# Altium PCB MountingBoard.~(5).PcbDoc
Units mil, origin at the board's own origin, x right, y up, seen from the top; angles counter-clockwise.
Board outline 3780 x 10000 mil, 4 copper layers (Top Layer, Internal Plane 1, Internal Plane 2, Bottom Layer); 23 components, 8 nets, 78 pads, 8 vias.
Unrouted connection lines stored in the file: 72.
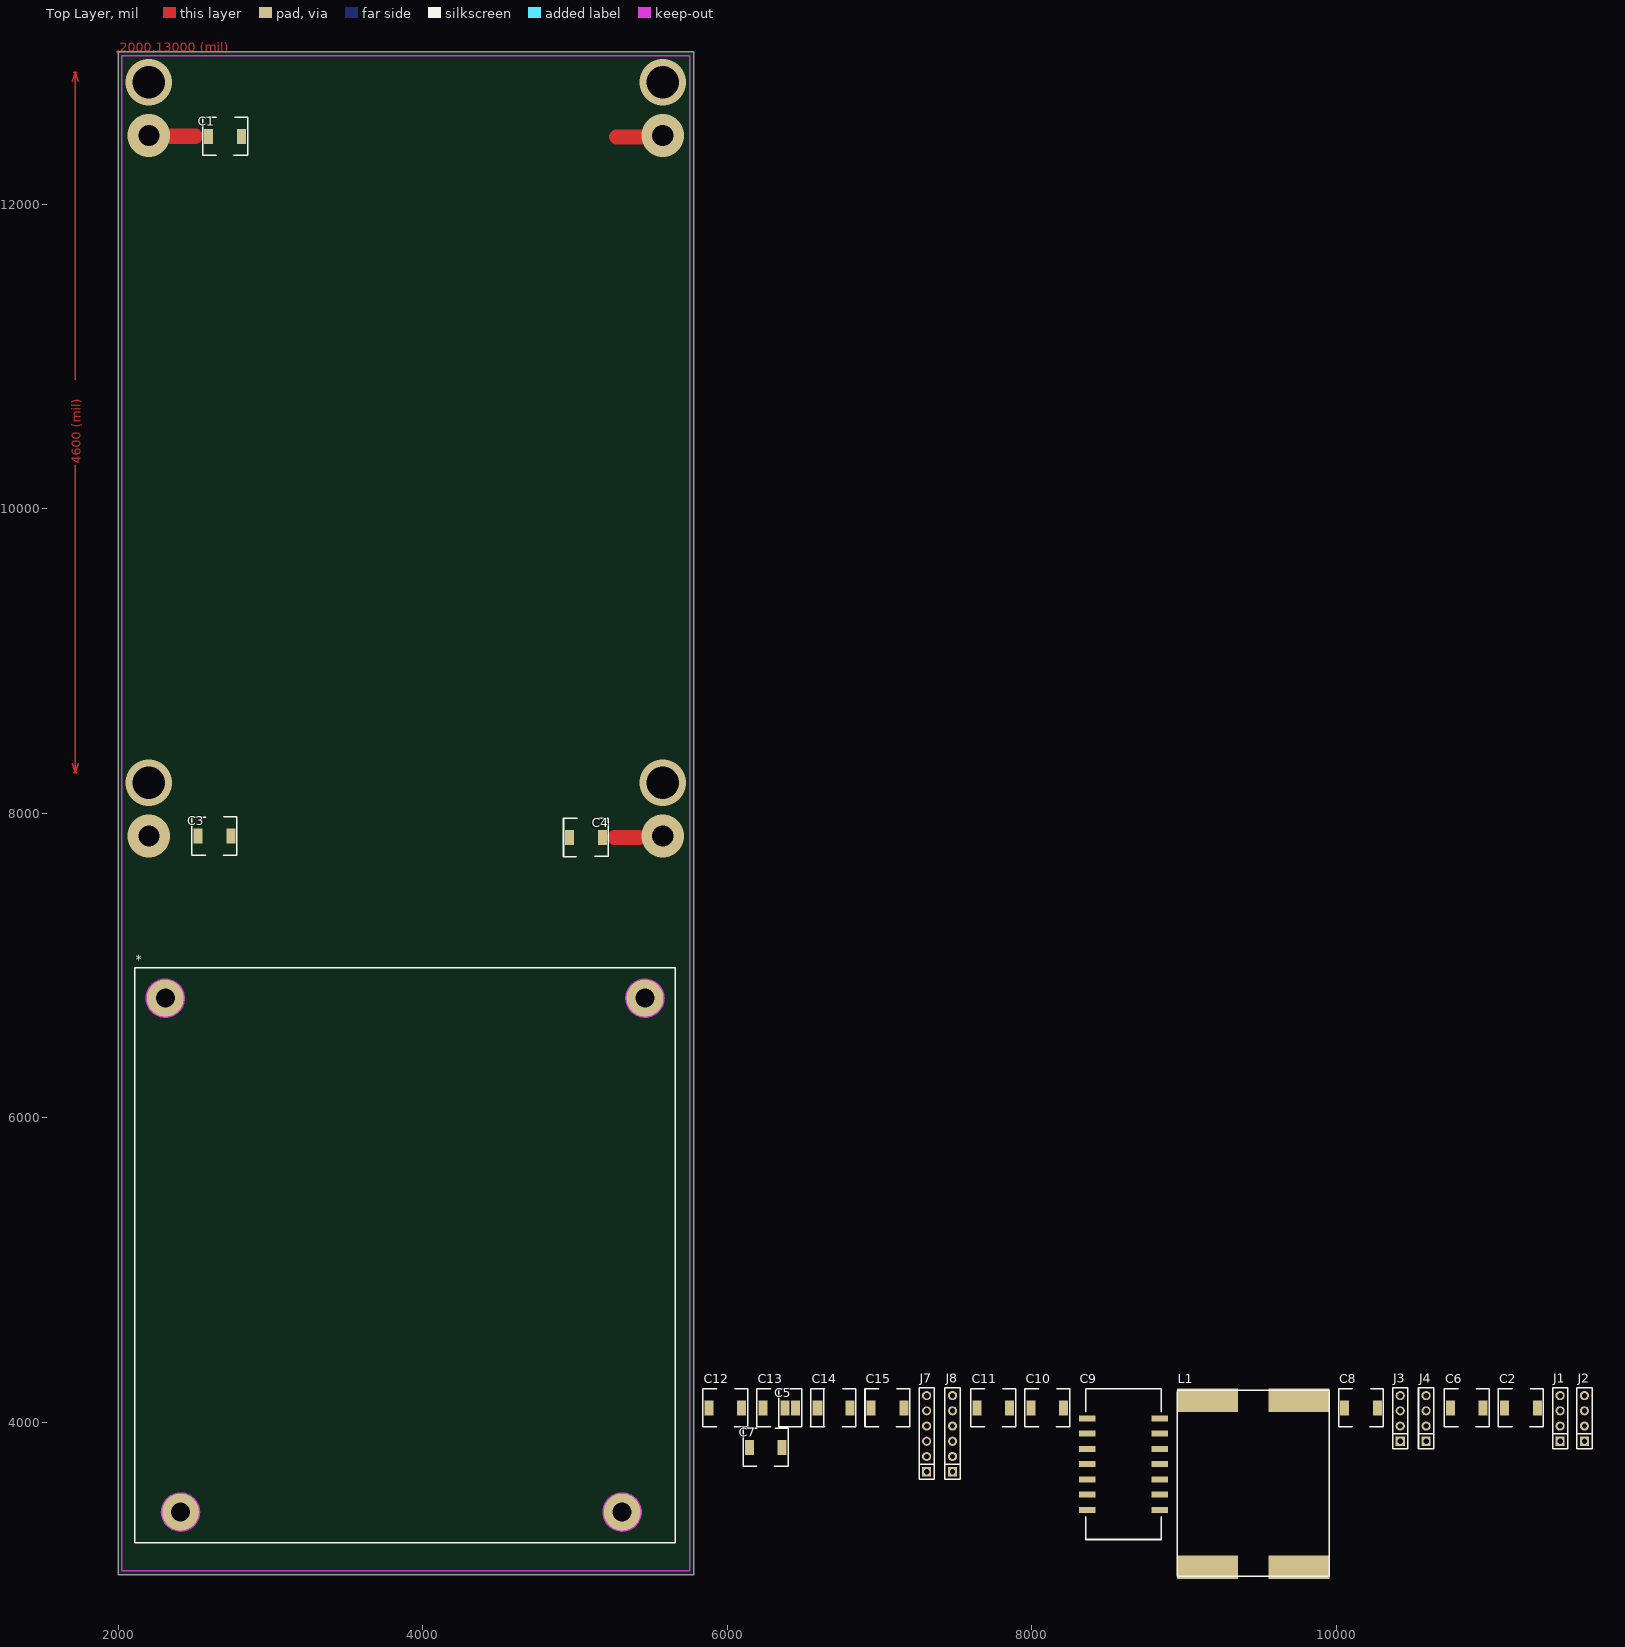
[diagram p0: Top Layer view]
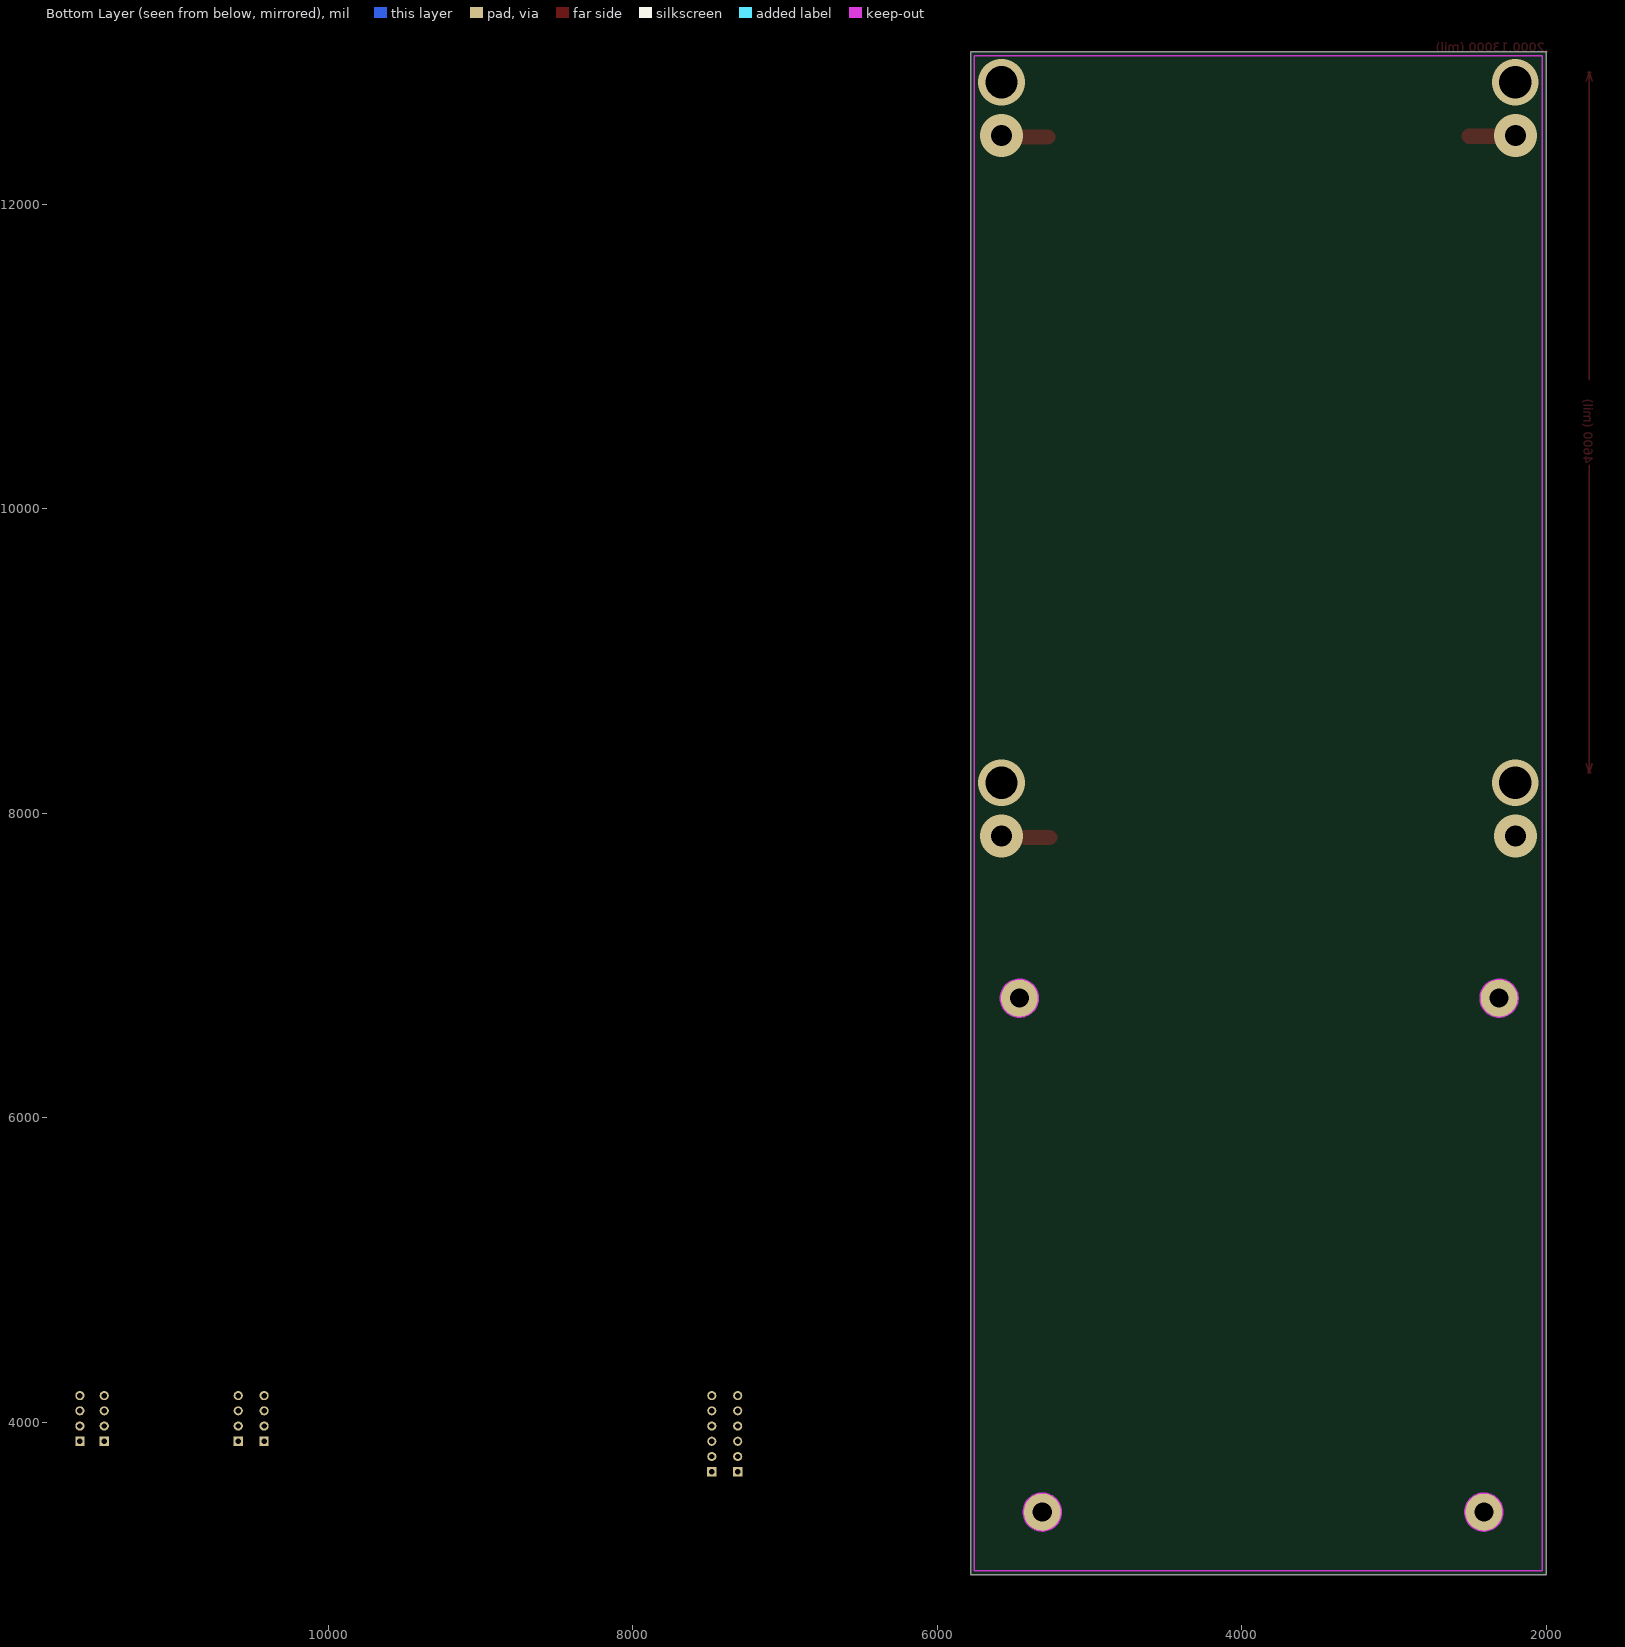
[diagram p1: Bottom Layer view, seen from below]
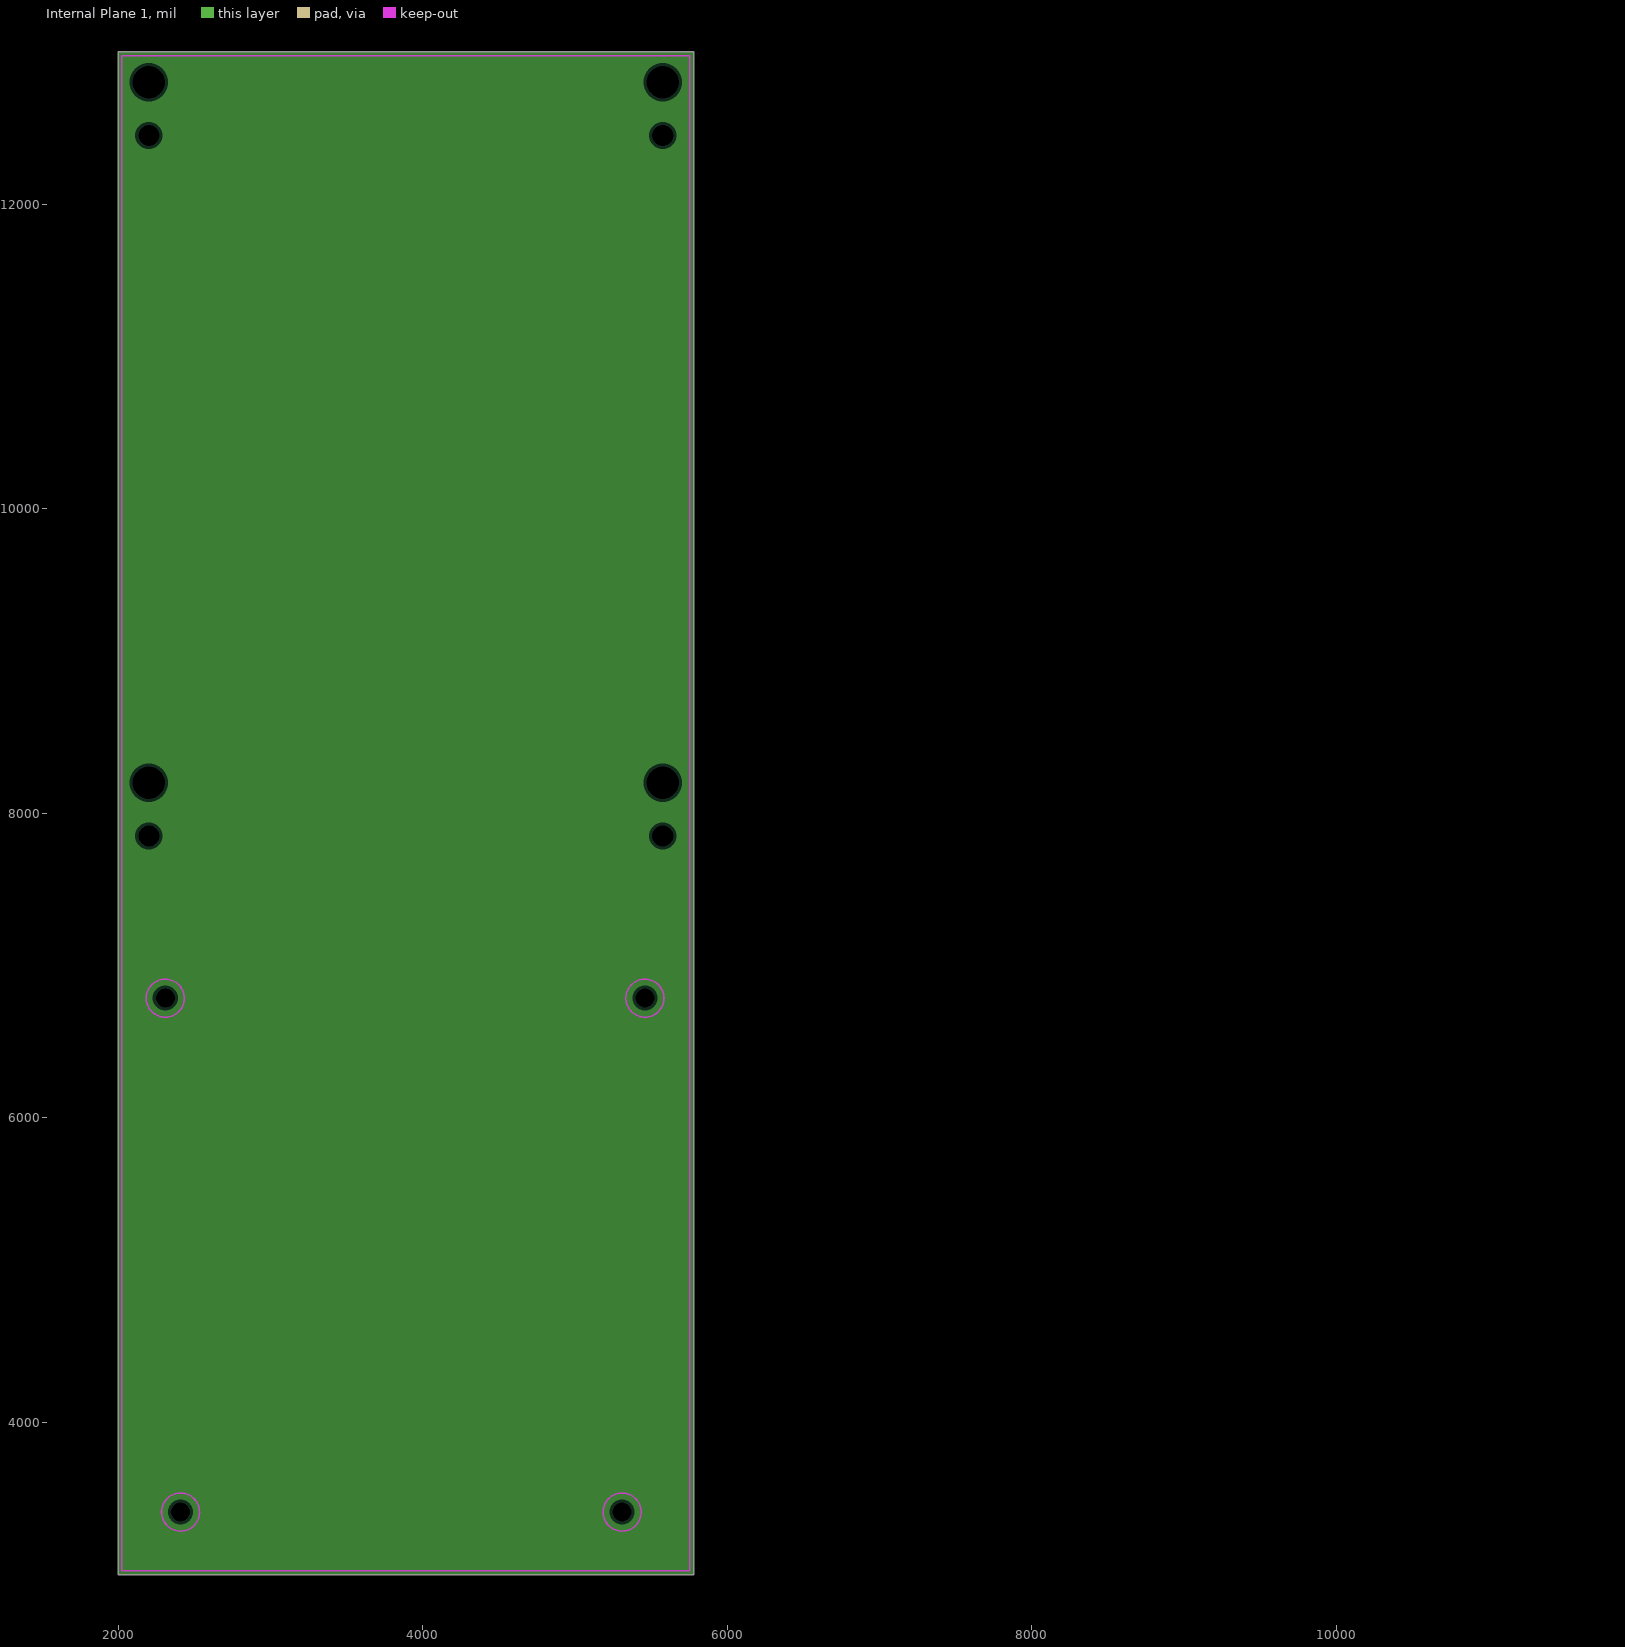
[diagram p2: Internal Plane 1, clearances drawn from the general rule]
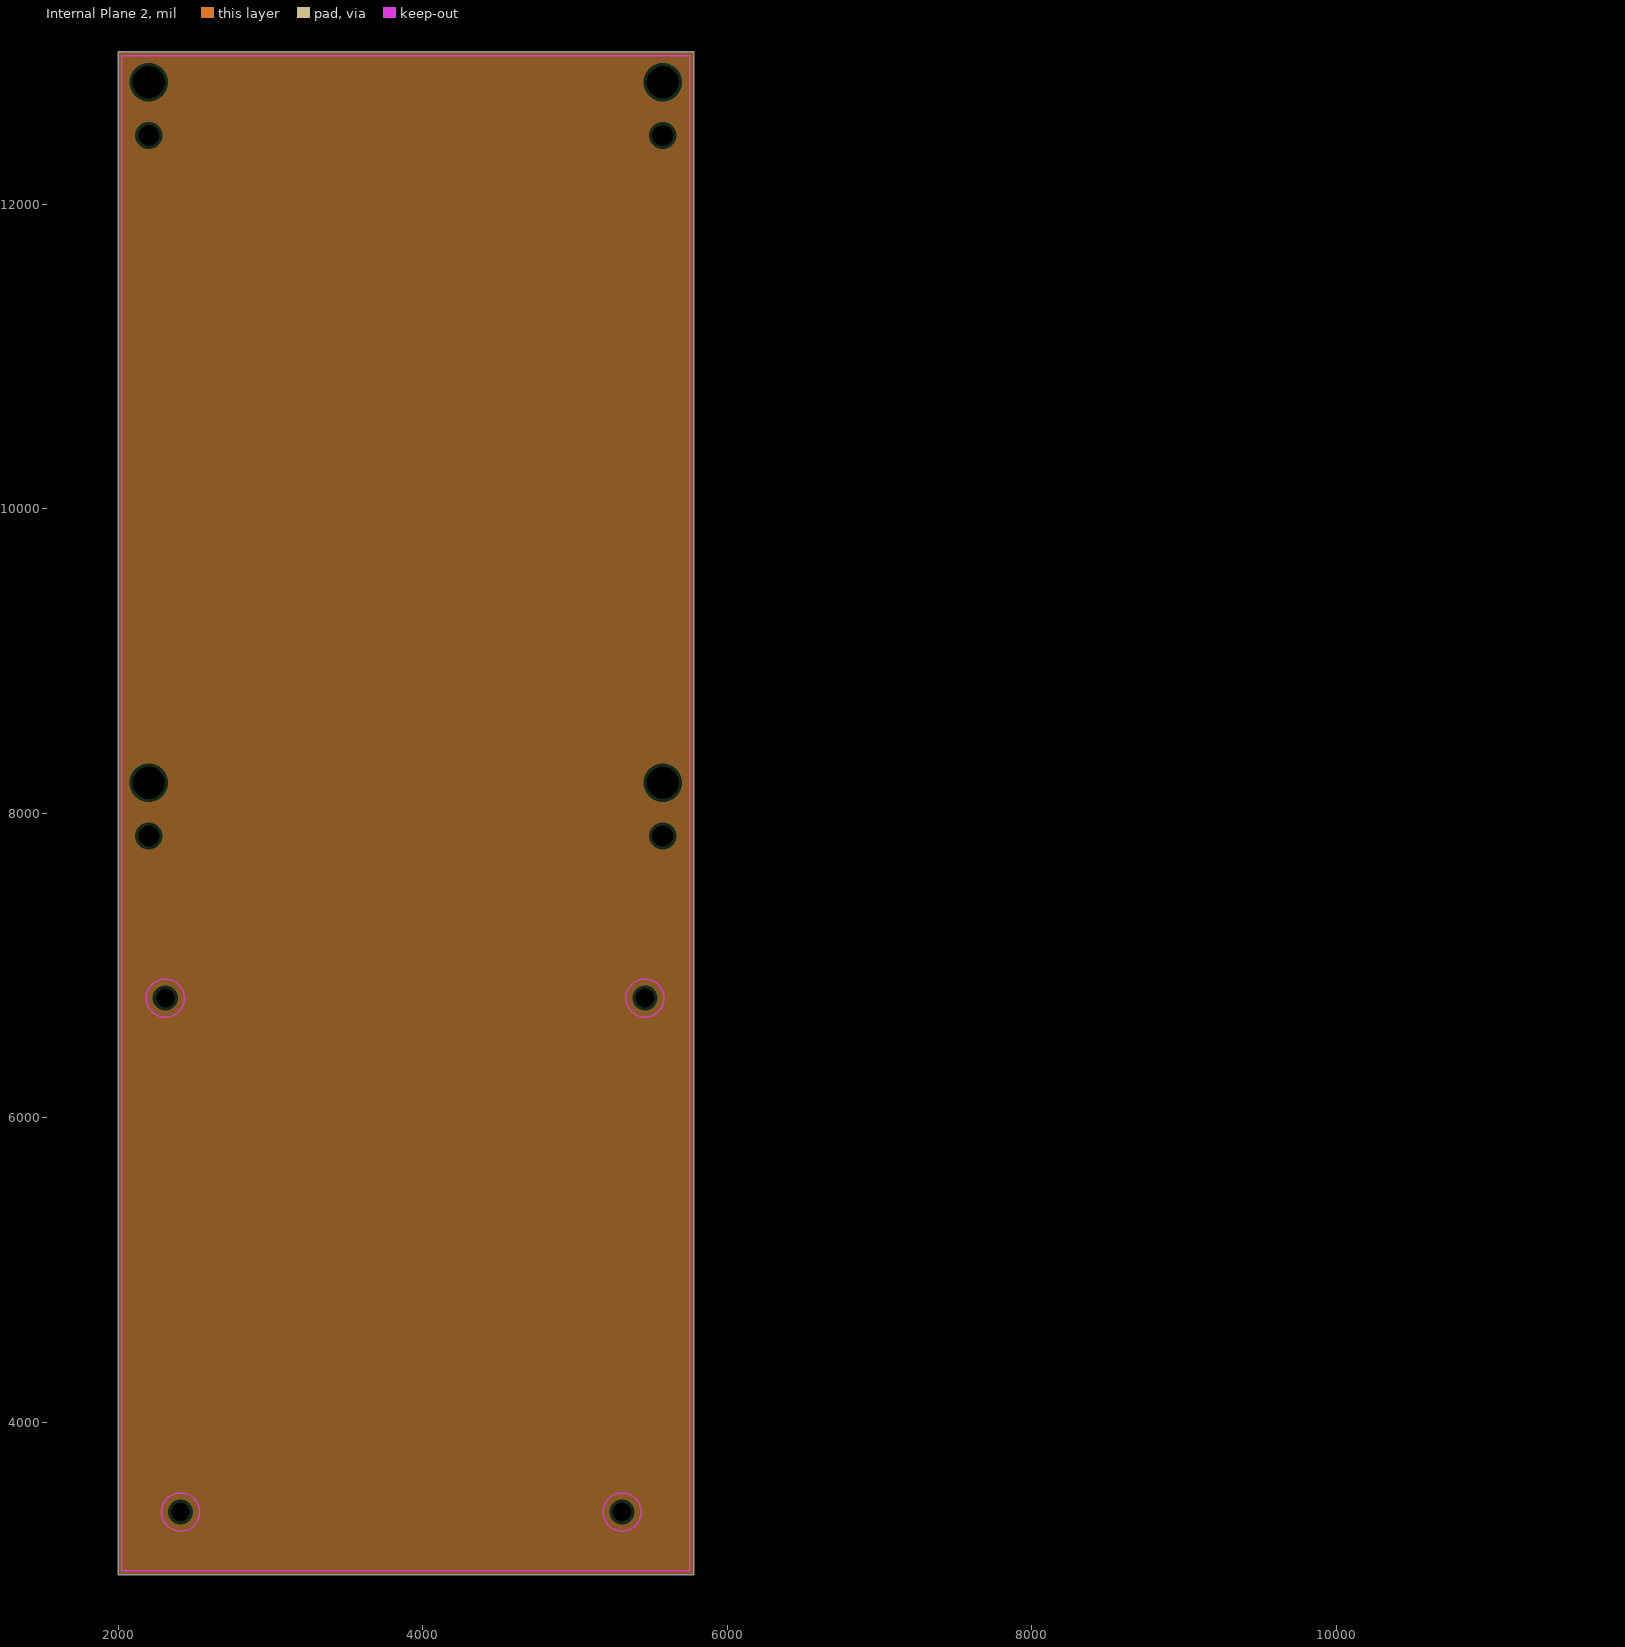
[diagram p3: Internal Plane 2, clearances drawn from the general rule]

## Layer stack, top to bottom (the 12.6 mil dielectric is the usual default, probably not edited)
Top Layer: signal copper 1.4
Dielectric: dielectric 12.6, FR-4, Dk 4.8
Internal Plane 1: plane copper 1.4
Dielectric: dielectric 12.6, FR-4, Dk 4.8
Internal Plane 2: plane copper 1.4
Dielectric: dielectric 12.6, FR-4, Dk 4.8
Bottom Layer: signal copper 1.4

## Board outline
2000,3000 5780,3000 5780,13000 2000,13000

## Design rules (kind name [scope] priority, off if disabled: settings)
Clearance [All] p1: gap=8
PlaneClearance [All] p1: clearance=20
PlaneConnect [All] p1: planeconnectstyle=Direct reliefexpansion=20 reliefentries=4 reliefconductorwidth=10 reliefairgap=10
PolygonConnect [All] p1: connectstyle=Direct reliefconductorwidth=10 reliefentries=4 polygonreliefangle="90 Angle"
RoomDefinition MountingBoard [InComponentClass('MountingBoard')] p1: confinementstyle=ConfineIn formatcopy=TRUE lockcomponents=FALSE outline 5825,3060 9400,3060 9400,6940 5825,6940
RoutingVias [All] p1: holewidth=28 width=50 viastyle="Through Hole" minholewidth=28 minwidth=50 maxholewidth=28 maxwidth=50
SilkscreenOverComponentPads [All] p1: minsilkscreentomaskgap=10
SolderMaskExpansion [All] p1: expansion=4
Width [All] p1: maxlimit=10 minlimit=10 preferedwidth=10
25 further rules are at their usual default settings.

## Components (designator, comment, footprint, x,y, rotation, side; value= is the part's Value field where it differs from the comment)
* "PC104 Footprint" "PC104 Footprint" 5460,6780 r180 top
C1 "Cap Semi" 7163 2595,12445 r0 top
C2 "Cap Semi" 7163 11105,4095 r0 top
C3 "Cap Semi" 7163 2525,7850 r0 top
C4 "Cap Semi" 7163 5180,7840 r180 top
C5 "Cap Semi" 7163 6380,4095 r0 top
C6 "Cap Semi" 7163 10750,4095 r0 top
C7 "Cap Semi" 7163 6145,3835 r0 top
C8 "Cap Semi" 7163 10055,4095 r0 top
C9 "10uf" CAPSTICK-CS4-7-SMD 8365,3425 r90 top
C10 "Cap Semi" 7163 7995,4095 r0 top
C11 "Cap Semi" 7163 7640,4095 r0 top
C12 "Cap Semi" 7163 5880,4095 r0 top
C13 "Cap Semi" 7163 6235,4095 r0 top
C14 "Cap Semi" 7163 6590,4095 r0 top
C15 "Cap Semi" 7163 6945,4095 r0 top
J1 "CON4" SIP4 11470,3875 r90 top
J2 "CON4" SIP4 11630,3875 r90 top
J3 "CON4" SIP4 10420,3875 r90 top
J4 "CON4" SIP4 10590,3875 r90 top
J7 "CON6" SIP6 7310,3675 r90 top
J8 "CON6" SIP6 7480,3675 r90 top
L1 "" Pulse_BigFoot 8955,2970 r90 top

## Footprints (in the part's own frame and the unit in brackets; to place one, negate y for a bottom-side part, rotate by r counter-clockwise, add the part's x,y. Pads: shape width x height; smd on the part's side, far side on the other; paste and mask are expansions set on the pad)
7163 [mm] "7.1 x 6.3 SMD"
  rect 1.5x2.5 smd: 1(0,0) 2(5.461,0)
  silkscreen extent -1.02,-3.17 6.48,3.17
CAPSTICK-CS4-7-SMD [mil] "Capstick CS4 case with 7 leads per side"
  rect 40x110 smd: 1(0,0) 1(100,0) 1(200,0) 1(300,0) 1(400,0) 1(500,0) 1(600,0) 2(0,-475) 2(100,-475) 2(200,-475) 2(300,-475) 2(400,-475) 2(500,-475) 2(600,-475)
  silkscreen extent -195,-485 795,10
"PC104 Footprint" [mil] "PC104 Footprint"
  round 250 hole 125: Mnt1(0,-5) Mnt2(150,3370) Mnt3(3050,3370) Mnt4(3150,-5)
  Keep-Out Layer circle w10: c0,-5 r125
  Keep-Out Layer circle w10: c150,3370 r125
  Keep-Out Layer circle w10: c3050,3370 r125
  Keep-Out Layer circle w10: c3150,-5 r125
  silkscreen extent -200,-205 3350,3570
Pulse_BigFoot [mil] "Pulse engineering big foot footprint"
  rect 155x400 smd: 1(77.5,-200) 2(77.5,-800) 3(1174.5,-200) 4(1174.5,-800)
  silkscreen extent 20,-1000 1240,0
SIP4 [mil]
  rect 60x60 hole 35: 1(0,0)
  round 60 hole 35: 2(100,0) 3(200,0) 4(300,0)
  silkscreen extent -50,-50 350,50
SIP6 [mil]
  rect 60x60 hole 35: 1(0,0)
  round 60 hole 35: 2(100,0) 3(200,0) 4(300,0) 5(400,0) 6(500,0)
  silkscreen extent -50,-50 550,50

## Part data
C1 C2 C3 C4 C5 C6 C7 C8 C10 C11 C12 C13 C14 C15: "Capacitor (Semiconductor SIM Model)"
C9: library part CAPACITOR, "Capacitor"
J1 J2 J3 J4 J7 J8: "Connector"
L1: library part "COMMON MODE CHOKE"

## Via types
v1: diameter 280, hole 140, Top Layer to Bottom Layer, 4 vias
v2: diameter 306, hole 213, Top Layer to Bottom Layer, 4 vias

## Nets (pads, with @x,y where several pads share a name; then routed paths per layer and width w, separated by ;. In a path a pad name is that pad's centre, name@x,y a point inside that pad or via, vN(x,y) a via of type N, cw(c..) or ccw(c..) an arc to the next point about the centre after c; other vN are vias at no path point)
48V+: L1.1
48V-: L1.3
+5V: C1.1 C7.1 C12.2 C13.2 J1.1 J2.1 J3.1 J4.1 J7.5 J7.6 J8.5 J8.6
+12V: C6.2 C10.2 C14.2 J1.4 J2.4 J3.4 J4.4 J7.4 J8.4
-12V: C15.2 J7.3 J8.3
CHASSIS: C1.2 C2.1 C3.1 C4.1 C5.1 C6.1 C7.2 C8.1 C10.1 C11.2 C12.1 C13.1 C14.1 C15.1 | length 161.9
  Top Layer w100: 5260,7840 5421.85,7840
  other v1: 2202.5,7850 5577.5,7850
"EDGETECH GROUND": C2.2 C3.2 C4.2 C5.2 C9.2 C11.1 J1.2 J1.3 J2.2 J2.3 J3.2 J3.3 J4.2 J4.3 J7.1 J7.2 J8.1 J8.2 L1.4
  other v2: 2202.5,8200 5577.5,8200 2202.5,12800 5577.5,12800
"FILTER 48V+": C8.2 C9.1 L1.2
pads on no net: *.Mnt1 *.Mnt2 *.Mnt3 *.Mnt4
copper on no net: | length 4694.9
  Top Layer w10: 1699.01,8325.91 1719.01,8265.91 ; 1699.01,12805.91 1719.01,12865.91 ; 1709.01,8265.91 1729.01,8265.91 ; 1709.01,12865.91 1729.01,12865.91 ; 1719.01,10285 1719.01,8265.91 ; 1719.01,10846.83 1719.01,12865.91 ; 1739.01,8325.91 1719.01,8265.91 ; 1739.01,12805.91 1719.01,12865.91 ; 1990,13000 2010,13000 ; 2000,12990 2000,13010
  Top Layer w100: 2345,12445 2506.85,12445 ; 5273.15,12440 5435,12440
  other v1: 2202.5,12450 5577.5,12450

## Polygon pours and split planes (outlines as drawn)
no net on Internal Plane 1 (split plane): 5780,3000 2000,3000 2000,13000 5780,13000
no net on Internal Plane 2 (split plane): 5780,3000 2000,3000 2000,13000 5780,13000

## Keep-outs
Keep-Out Layer:
  lines w10: 2025,3025 2025,12975 5755,12975 5755,3025 2025,3025

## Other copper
Top Layer:
  text "2000,13000 (mil)" at 2010,13000 h60
  text "4600 (mil)" at 1755,10295 h60 r90

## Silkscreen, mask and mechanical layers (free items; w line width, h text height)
Drill Drawing:
  text ".LEGEND" at 5980,3200 h60
  text "Drill Drawing." at 5980,3100 h60

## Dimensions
2202.5,12800 to 5577.5,12800 on Top Layer
2025,3025 to 2025,12975 on Mechanical 1
2025,3025 to 5755,3025 on Mechanical 1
